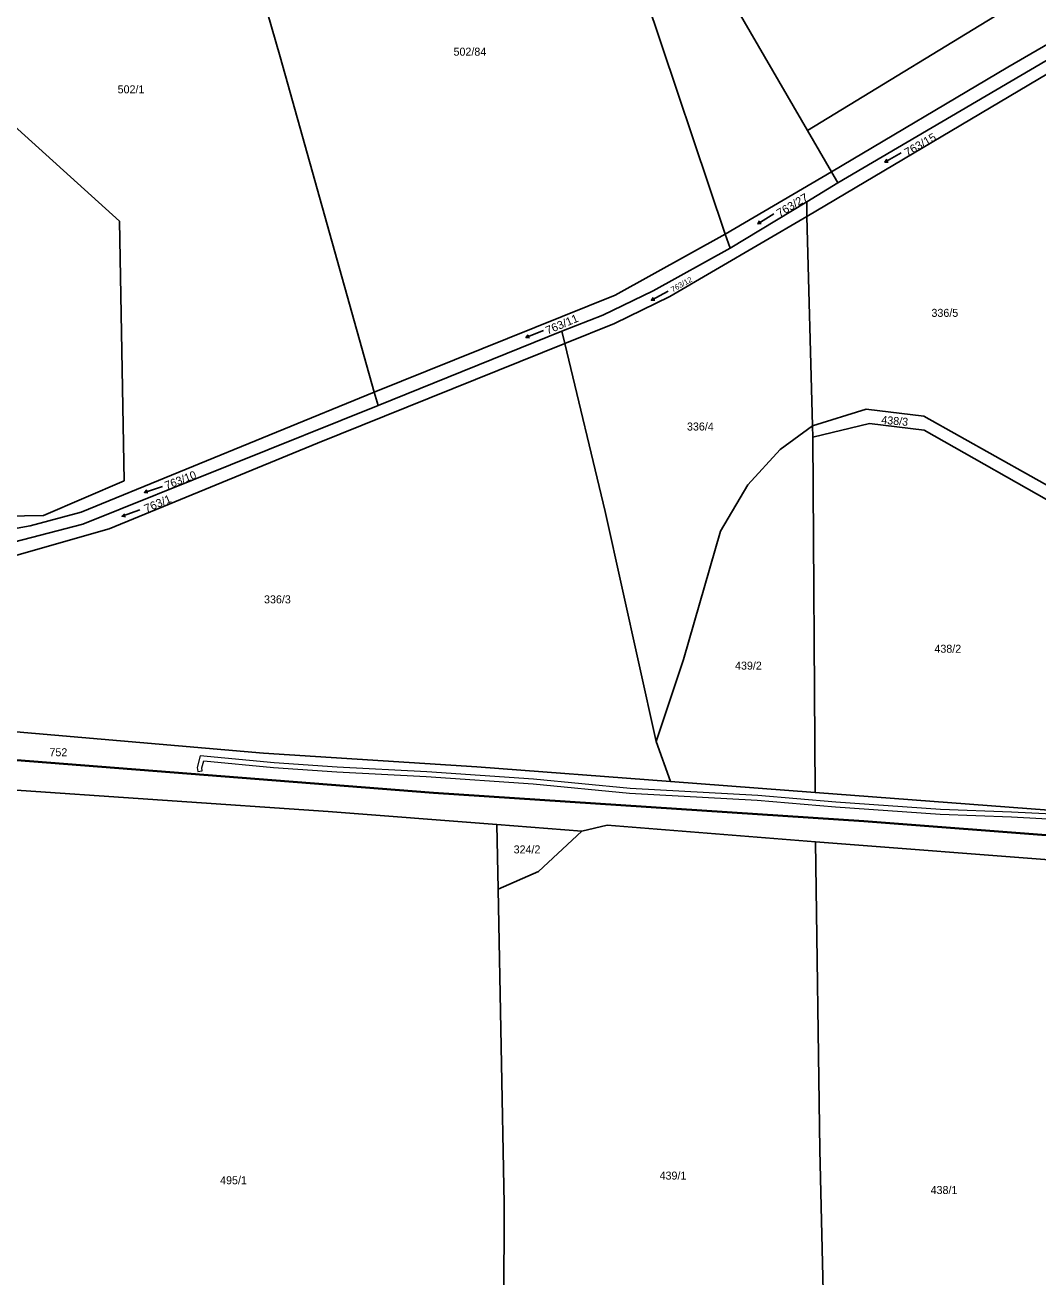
# Model space of a CAD drawing. Extents: x -701211 to -698780, y -1014269 to -1012378.
# Drawn here: x -699614.3 to -699399.1, y -1013138.2 to -1012872.2 of the extents above; entities that cross this region are included whole.
import ezdxf
from ezdxf.enums import TextEntityAlignment as Align

# ---------------------------------------------------------------- set-up
doc = ezdxf.new("R2010")
doc.units = 0
doc.header["$LTSCALE"] = 0.68
for name, color, linetype, lineweight in [('1', 7, 'Continuous', 25), ('13', 7, 'Continuous', 13), ('3', 7, 'Continuous', 25), ('6', 7, 'Continuous', 35)]:
    doc.layers.add(name, color=color, linetype=linetype, lineweight=lineweight)
doc.layers.add('2', color=7, linetype='Continuous')

msp = doc.modelspace()

# ---------------------------------------------------------------- linework, layer by layer
at = {"layer": '1'}
for p, q in [((-699560.16, -1012878.94), (-699575.33, -1012825.79)), ((-699490.38, -1012842.72), (-699465.56, -1012916.61)), ((-699405.52, -1012881.15), (-699349.71, -1012848.74)), ((-699448.1, -1012894.65), (-699467.88, -1012860.46)), ((-699448.1, -1012894.65), (-699402.57, -1012866.78)), ((-699633.39, -1012878.56), (-699594.25, -1012913.85)), ((-699540.14, -1012950.19), (-699560.16, -1012878.94)), ((-699441.64, -1012905.74), (-699395.43, -1012878.62)), ((-699448.25, -1012912.86), (-699394.98, -1012881.31)), ((-699442.99, -1012903.41), (-699405.52, -1012881.15)), ((-699442.99, -1012903.41), (-699448.1, -1012894.65)), ((-699465.56, -1012916.61), (-699442.99, -1012903.41)), ((-699441.64, -1012905.74), (-699442.99, -1012903.41)), ((-699448.22, -1012909.76), (-699441.64, -1012905.74)), ((-699464.56, -1012919.64), (-699448.22, -1012909.76)), ((-699448.22, -1012909.76), (-699448.25, -1012912.86)), ((-699594.25, -1012913.85), (-699593.27, -1012969.05)), ((-699477.33, -1012929.91), (-699448.25, -1012912.86)), ((-699448.25, -1012912.86), (-699447.05, -1012957.36)), ((-699488.98, -1012929.64), (-699465.56, -1012916.61)), ((-699465.56, -1012916.61), (-699464.56, -1012919.64)), ((-699464.56, -1012919.64), (-699480.9, -1012928.71)), ((-699540.14, -1012950.19), (-699488.98, -1012929.64)), ((-699480.9, -1012928.71), (-699491.58, -1012933.83)), ((-699489.08, -1012935.66), (-699477.33, -1012929.91)), ((-699491.58, -1012933.83), (-699500.32, -1012937.22)), ((-699499.67, -1012939.87), (-699489.08, -1012935.66)), ((-699539.3, -1012953.05), (-699500.32, -1012937.22)), ((-699500.32, -1012937.22), (-699499.67, -1012939.87)), ((-699552.17, -1012961.06), (-699499.67, -1012939.87)), ((-699491.12, -1012975.59), (-699499.67, -1012939.87)), ((-699602.42, -1012975.68), (-699540.14, -1012950.19)), ((-699539.3, -1012953.05), (-699540.14, -1012950.19)), ((-699602.03, -1012978.27), (-699539.3, -1012953.05)), ((-699447.05, -1012957.36), (-699435.65, -1012953.86)), ((-699435.65, -1012953.86), (-699423.42, -1012955.33)), ((-699434.94, -1012956.91), (-699446.98, -1012959.78)), ((-699423.33, -1012958.29), (-699434.94, -1012956.91)), ((-699385.19, -1012976.78), (-699423.42, -1012955.33)), ((-699447.05, -1012957.36), (-699453.94, -1012962.38)), ((-699447.05, -1012957.36), (-699446.98, -1012959.78)), ((-699388.78, -1012977.9), (-699423.33, -1012958.29)), ((-699596.5, -1012979.28), (-699552.17, -1012961.06)), ((-699446.98, -1012959.78), (-699446.49, -1013035.27)), ((-699453.94, -1012962.38), (-699460.76, -1012969.93)), ((-699593.27, -1012969.05), (-699610.43, -1012976.41)), ((-699460.76, -1012969.93), (-699466.62, -1012979.72)), ((-699480.26, -1013024.43), (-699491.12, -1012975.59)), ((-699621.55, -1012983.3), (-699602.03, -1012978.27)), ((-699613.28, -1012978.64), (-699602.42, -1012975.68)), ((-699622.53, -1012980.26), (-699613.28, -1012978.64)), ((-699617.05, -1012985.11), (-699596.5, -1012979.28)), ((-699474.43, -1013007.01), (-699466.62, -1012979.72)), ((-699480.26, -1013024.43), (-699474.43, -1013007.01)), ((-699632.72, -1013020.93), (-699563.71, -1013026.94)), ((-699480.26, -1013024.43), (-699477.2, -1013032.93)), ((-699563.71, -1013026.94), (-699518.35, -1013029.8)), ((-699518.35, -1013029.8), (-699477.2, -1013032.93)), ((-699630.2, -1013033.84), (-699549.93, -1013039.34)), ((-699477.2, -1013032.93), (-699446.49, -1013035.27)), ((-699446.49, -1013035.27), (-699390.16, -1013039.55)), ((-699549.93, -1013039.34), (-699514.08, -1013042.11)), ((-699514.08, -1013042.11), (-699496.05, -1013043.51)), ((-699513.81, -1013055.83), (-699514.08, -1013042.11)), ((-699496.05, -1013043.51), (-699505.27, -1013052.06)), ((-699496.05, -1013043.51), (-699490.67, -1013042.25)), ((-699490.67, -1013042.25), (-699446.4, -1013045.78)), ((-699445.46, -1013111.19), (-699446.4, -1013045.78)), ((-699446.4, -1013045.78), (-699390.54, -1013050.06)), ((-699505.27, -1013052.06), (-699513.81, -1013055.83)), ((-699512.53, -1013122.7), (-699513.81, -1013055.83)), ((-699443.69, -1013188.24), (-699445.46, -1013111.19)), ((-699512.75, -1013186.27), (-699512.53, -1013122.7))]:
    msp.add_line(p, q, dxfattribs=at)
msp.add_lwpolyline([(-699610.43, -1012976.41), (-699671.34, -1012977.47), (-699674.33, -1012977.55)], dxfattribs=at)
at = {"layer": '13'}
msp.add_lwpolyline([(-699391.73, -1013040.13), (-699404.79, -1013039.45), (-699419.85, -1013038.88), (-699442.07, -1013037.35), (-699458.67, -1013035.9), (-699485.8, -1013034.43), (-699506.32, -1013032.46), (-699528.97, -1013030.89), (-699548.02, -1013029.88), (-699561.44, -1013028.95), (-699577.12, -1013027.5), (-699577.8, -1013029.99), (-699577.66, -1013030.84), (-699576.68, -1013030.67), (-699576.78, -1013030.05), (-699576.38, -1013028.58), (-699561.52, -1013029.95), (-699548.13, -1013030.87), (-699529.1, -1013031.88), (-699506.41, -1013033.45), (-699485.9, -1013035.43), (-699458.76, -1013036.9), (-699442.12, -1013038.35), (-699419.89, -1013039.88), (-699404.75, -1013040.45), (-699391.84, -1013041.13)], dxfattribs=at)
at = {"layer": '3'}
for p, q in [((-699431.664, -1012901.356), (-699431.265, -1012900.737)), ((-699458.647, -1012914.456), (-699458.27, -1012913.825)), ((-699481.278, -1012930.674), (-699480.857, -1012930.07)), ((-699507.909, -1012938.579), (-699507.418, -1012938.031)), ((-699588.974, -1012971.519), (-699588.455, -1012970.997)), ((-699593.732, -1012976.586), (-699593.231, -1012976.046))]:
    msp.add_line(p, q, dxfattribs=at)
for points in [[(-699428.182, -1012899.346), (-699431.664, -1012901.356), (-699430.929, -1012901.319)], [(-699455.238, -1012912.326), (-699458.647, -1012914.456), (-699457.914, -1012914.394)], [(-699477.728, -1012928.787), (-699481.278, -1012930.674), (-699480.542, -1012930.663)], [(-699504.156, -1012937.138), (-699507.909, -1012938.579), (-699507.178, -1012938.658)], [(-699585.151, -1012970.277), (-699588.974, -1012971.519), (-699588.248, -1012971.636)], [(-699589.954, -1012975.211), (-699593.732, -1012976.586), (-699593.001, -1012976.678)]]:
    msp.add_lwpolyline(points, dxfattribs=at)
at = {"layer": '6'}
for p, q in [((-699628, -1013027.5), (-699527.57, -1013035.36)), ((-699527.57, -1013035.36), (-699436.1, -1013041.4)), ((-699436.1, -1013041.4), (-699351.01, -1013047.96))]:
    msp.add_line(p, q, dxfattribs=at)

# ---------------------------------------------------------------- texts
at = {"layer": '2'}
for s, p in [('502/84', (-699519.83, -1012878.715)), ('502/1', (-699591.82, -1012886.715)), ('336/5', (-699418.92, -1012934.215)), ('336/4', (-699470.86, -1012958.365)), ('336/3', (-699560.72, -1012995.095)), ('438/2', (-699418.29, -1013005.585)), ('439/2', (-699460.65, -1013009.175)), ('324/2', (-699507.69, -1013048.225)), ('439/1', (-699476.68, -1013117.535)), ('495/1', (-699570.05, -1013118.525)), ('438/1', (-699419.1, -1013120.605))]:
    msp.add_text(s, height=1.7, dxfattribs=at).set_placement(p, align=Align.CENTER)
at = {"layer": '2', "width": 1.05}
for s, height, rotation, p in [('763/15', 1.7, 30, (-699423.741, -1012898.3431)), ('763/27', 1.7, 31, (-699450.8978, -1012911.1897)), ('763/12', 1.14, 29, (-699474.6003, -1012927.8211)), ('763/11', 1.7, 23, (-699499.9641, -1012936.5688)), ('763/1', 1.7, 23, (-699585.8341, -1012974.669))]:
    msp.add_text(s, height=height, rotation=rotation, dxfattribs=at).set_placement(p, align=Align.CENTER)
at = {"layer": '2'}
for s, rotation, p in [('438/3', 355, (-699429.6391, -1012957.1565)), ('763/10', 21, (-699581.0221, -1012969.6874))]:
    msp.add_text(s, height=1.7, rotation=rotation, dxfattribs=at).set_placement(p, align=Align.CENTER)
msp.add_text('752', height=1.7, dxfattribs=at).set_placement((-699609.15, -1013027.575))

doc.saveas('drawing.dxf')
